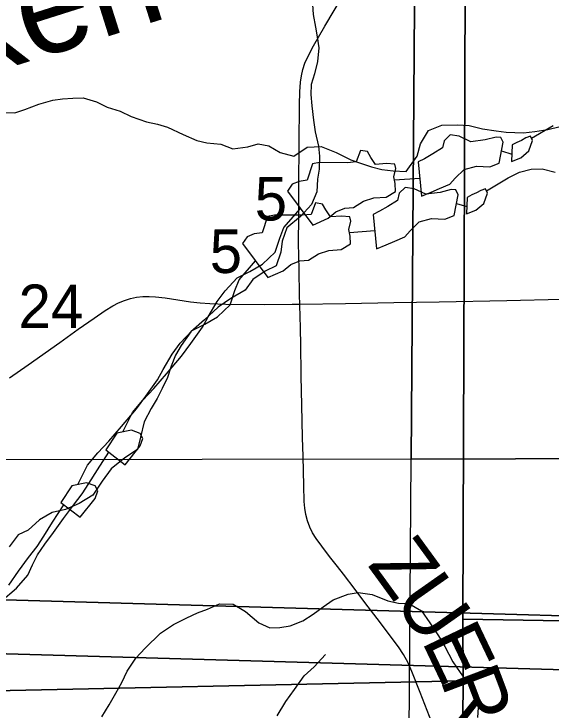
# Model space of a CAD drawing. Extents: x -21.1 to 50.3, y -4.9 to 22.1.
# Drawn here: x 4.071 to 4.587, y 17.902 to 18.571 of the extents above; entities that cross this region are included whole.
import ezdxf

# ---------------------------------------------------------------- set-up
doc = ezdxf.new("R2010")
doc.units = 0
for name, color, linetype in [('GM_X_County_Road', 7, 'Continuous'), ('GM_X_Minor_Lake', 7, 'Continuous'), ('GM_X_Minor_River', 7, 'Continuous'), ('GM_X_Minor_River_Text', 7, 'Continuous'), ('GM_X_Section', 7, 'Continuous'), ('GM_X_Section_Text', 7, 'Continuous'), ('GM_X_Township_Road', 7, 'Continuous'), ('GM_X_Township_Road_Text', 7, 'Continuous')]:
    doc.layers.add(name, color=color, linetype=linetype)

msp = doc.modelspace()

# ---------------------------------------------------------------- linework, layer by layer
at = {"layer": 'GM_X_County_Road'}
for points in [[(4.06655, 18.22107), (4.08439, 18.23347), (4.11483, 18.25489), (4.13257, 18.26786), (4.1479, 18.27834), (4.15838, 18.28565), (4.16583, 18.29006), (4.17135, 18.29295), (4.17698, 18.29535), (4.18275, 18.29722), (4.18872, 18.29843), (4.19477, 18.29909), (4.20088, 18.29926), (4.20699, 18.29899), (4.21614, 18.29795), (4.2406, 18.29407), (4.24986, 18.29298), (4.25917, 18.2923), (4.27471, 18.29175), (4.31197, 18.29148), (4.33843, 18.29178), (4.3458, 18.29178)], [(4.3458, 18.29178), (4.3896, 18.29249), (4.43621, 18.29326), (4.4797, 18.29415), (4.54492, 18.29528), (4.59772, 18.29648)]]:
    msp.add_lwpolyline(points, dxfattribs=at)
at = {"layer": 'GM_X_Minor_Lake'}
for points in [[(4.46292, 18.3955), (4.47198, 18.39939), (4.48028, 18.4029), (4.49009, 18.40718), (4.49534, 18.41293), (4.50397, 18.42137), (4.51569, 18.42453), (4.52859, 18.42391), (4.53765, 18.42742), (4.54122, 18.44757), (4.53927, 18.4521), (4.53472, 18.45243), (4.52413, 18.44966), (4.51012, 18.44799), (4.49906, 18.45319), (4.49032, 18.45461), (4.4847, 18.44886), (4.48288, 18.44201), (4.47384, 18.43622), (4.46555, 18.43158), (4.45952, 18.42848)], [(4.54939, 18.42906), (4.55845, 18.43257), (4.56596, 18.43911), (4.56965, 18.44901), (4.5677, 18.45316), (4.56317, 18.4516), (4.55902, 18.44927), (4.55449, 18.44733), (4.54997, 18.445)], [(4.35818, 18.36782), (4.3729, 18.37443), (4.38041, 18.38058), (4.3891, 18.38409), (4.39743, 18.38456), (4.40685, 18.39073), (4.41705, 18.39387), (4.4288, 18.39476), (4.43784, 18.40017), (4.43737, 18.40775), (4.43616, 18.41419), (4.43797, 18.42217), (4.43716, 18.42634), (4.42919, 18.42701), (4.41858, 18.42614), (4.41396, 18.43292), (4.41086, 18.43858), (4.40402, 18.43965), (4.39997, 18.4286), (4.39164, 18.42775), (4.36471, 18.42784), (4.3579, 18.42663), (4.35276, 18.41102), (4.34519, 18.4098), (4.3384, 18.40707), (4.33392, 18.40057)], [(4.54997, 18.445), (4.54939, 18.42906)], [(4.45952, 18.42848), (4.46292, 18.3955)], [(4.33392, 18.40057), (4.35818, 18.36782)], [(4.41963, 18.34499), (4.42869, 18.34888), (4.43699, 18.35238), (4.44681, 18.35666), (4.45205, 18.36241), (4.46068, 18.37085), (4.4724, 18.37401), (4.4853, 18.37339), (4.49436, 18.3769), (4.49793, 18.39705), (4.49598, 18.40158), (4.49143, 18.40191), (4.48084, 18.39915), (4.46683, 18.39748), (4.45577, 18.40267), (4.44703, 18.40409), (4.44141, 18.39834), (4.43959, 18.39149), (4.43055, 18.3857), (4.42226, 18.38106), (4.41623, 18.37796)], [(4.5061, 18.37855), (4.51516, 18.38206), (4.52267, 18.38859), (4.52636, 18.3985), (4.52441, 18.40265), (4.51988, 18.40108), (4.51573, 18.39876), (4.5112, 18.39681), (4.50668, 18.39449)], [(4.50668, 18.39449), (4.5061, 18.37855)], [(4.31489, 18.3173), (4.32961, 18.32391), (4.33712, 18.33006), (4.34581, 18.33357), (4.35414, 18.33404), (4.36356, 18.34021), (4.37376, 18.34336), (4.38551, 18.34424), (4.39455, 18.34965), (4.39408, 18.35723), (4.39288, 18.36367), (4.39468, 18.37166), (4.39388, 18.37582), (4.3859, 18.3765), (4.37529, 18.37563), (4.37067, 18.3824), (4.36757, 18.38807), (4.36073, 18.38913), (4.35668, 18.37808), (4.34835, 18.37723), (4.32142, 18.37732), (4.31461, 18.37611), (4.30948, 18.3605), (4.30191, 18.35928), (4.29511, 18.35655), (4.29063, 18.35005)], [(4.41623, 18.37796), (4.41963, 18.34499)], [(4.29063, 18.35005), (4.31489, 18.3173)], [(4.17759, 18.13746), (4.19218, 18.15545), (4.19475, 18.16268), (4.19204, 18.16759), (4.18367, 18.17053), (4.16967, 18.16773), (4.15923, 18.15168)], [(4.15923, 18.15168), (4.17759, 18.13746)], [(4.1343, 18.08694), (4.14889, 18.10493), (4.15146, 18.11217), (4.14875, 18.11707), (4.14038, 18.12002), (4.12638, 18.11721), (4.11594, 18.10116)], [(4.11594, 18.10116), (4.1343, 18.08694)]]:
    msp.add_lwpolyline(points, dxfattribs=at)
at = {"layer": 'GM_X_Minor_River'}
for points in [[(4.35796, 18.57986), (4.35871, 18.57038), (4.36098, 18.55824), (4.36249, 18.54876), (4.364, 18.53814), (4.36286, 18.52524), (4.35982, 18.51311), (4.35678, 18.50287), (4.3564, 18.49338), (4.35715, 18.48239), (4.35904, 18.46873), (4.36055, 18.45736), (4.36358, 18.4437), (4.36471, 18.43422), (4.36432, 18.4217), (4.3628, 18.41184), (4.36204, 18.39971), (4.3571, 18.38757), (4.34648, 18.37619), (4.33321, 18.36519), (4.32865, 18.35229), (4.32751, 18.34167), (4.32295, 18.32878), (4.31234, 18.32347), (4.30058, 18.3155), (4.293, 18.30526), (4.27935, 18.29729), (4.26721, 18.28895), (4.25394, 18.27681), (4.24104, 18.26505), (4.23156, 18.25215), (4.22625, 18.24267), (4.22207, 18.23205), (4.21828, 18.22143), (4.21334, 18.21081), (4.20841, 18.20095), (4.20272, 18.19147), (4.19589, 18.17857), (4.19247, 18.16378), (4.18943, 18.15202), (4.1773, 18.14406), (4.1644, 18.13344), (4.15568, 18.12168), (4.14658, 18.10802), (4.1333, 18.10005), (4.12041, 18.09437), (4.10752, 18.09133), (4.09539, 18.0845), (4.08439, 18.07464), (4.07491, 18.07009), (4.06619, 18.05833)], [(4.05737, 18.47617), (4.07141, 18.47565), (4.08131, 18.47896), (4.09465, 18.48415), (4.10798, 18.48781), (4.11748, 18.48923), (4.12736, 18.48989), (4.13723, 18.49017), (4.15009, 18.48624), (4.16029, 18.4812), (4.17278, 18.47728), (4.18336, 18.47223), (4.19811, 18.46715), (4.20871, 18.46476), (4.21855, 18.462), (4.23367, 18.45501), (4.24651, 18.44918), (4.25636, 18.4468), (4.26963, 18.44553), (4.28135, 18.44123), (4.2958, 18.44298), (4.3057, 18.44592), (4.31592, 18.44392), (4.32687, 18.43773), (4.34012, 18.43418), (4.35274, 18.44279), (4.36641, 18.44341), (4.38077, 18.43757), (4.39474, 18.43059), (4.40496, 18.42706), (4.4148, 18.42393), (4.42464, 18.42117), (4.43563, 18.41992), (4.44815, 18.41941), (4.45856, 18.43412), (4.46171, 18.44586), (4.46944, 18.4587), (4.4824, 18.46389), (4.49758, 18.46411), (4.50859, 18.46362), (4.52146, 18.46045), (4.53473, 18.45842), (4.5442, 18.45718), (4.5609, 18.45663), (4.57192, 18.45766), (4.58447, 18.45981), (4.59627, 18.46273)], [(4.56859, 18.45127), (4.58958, 18.46364)], [(4.53971, 18.43907), (4.54965, 18.4361)], [(4.5253, 18.40075), (4.54629, 18.41313), (4.55723, 18.41856), (4.56819, 18.42171), (4.57881, 18.42182), (4.59136, 18.41854)], [(4.43673, 18.41119), (4.46111, 18.41304)], [(4.49642, 18.38855), (4.50636, 18.38559)], [(4.17553, 18.1689), (4.18461, 18.18762), (4.19472, 18.19949), (4.20521, 18.21061), (4.21757, 18.22478), (4.23179, 18.24163), (4.24076, 18.25386), (4.25196, 18.26954), (4.25754, 18.27947), (4.26609, 18.29436), (4.27394, 18.30469), (4.28556, 18.31695), (4.29762, 18.32315), (4.30968, 18.33011), (4.32207, 18.34163), (4.32647, 18.35534), (4.33052, 18.36563), (4.34626, 18.38391)], [(4.39344, 18.36067), (4.41782, 18.36252)], [(4.13224, 18.11839), (4.14132, 18.1371), (4.15143, 18.14897), (4.16192, 18.16009), (4.17428, 18.17426), (4.1885, 18.19111), (4.19747, 18.20335), (4.20867, 18.21903), (4.21425, 18.22895), (4.2228, 18.24384), (4.23065, 18.25417), (4.24227, 18.26644), (4.25433, 18.27264), (4.26639, 18.2796), (4.27878, 18.29111), (4.28318, 18.30482), (4.28723, 18.31511), (4.30298, 18.33339)], [(4.05809, 18.00602), (4.07311, 18.01871), (4.08397, 18.03134), (4.08841, 18.04126), (4.09323, 18.0508), (4.10033, 18.06112), (4.10892, 18.07221), (4.11825, 18.08559), (4.12797, 18.0986), (4.13619, 18.10931), (4.14291, 18.11925), (4.1511, 18.13262), (4.16212, 18.14944)], [(4.06563, 18.0217), (4.07496, 18.03508), (4.08468, 18.04808), (4.0929, 18.0588), (4.09962, 18.06873), (4.10781, 18.0821), (4.11883, 18.09892)], [(4.15534, 17.89495), (4.16235, 17.90662), (4.16861, 17.91792), (4.17446, 17.92809), (4.17957, 17.93902), (4.18812, 17.95143), (4.197, 17.96118), (4.21166, 17.97539), (4.22432, 17.98393), (4.23695, 17.9902), (4.24728, 17.99498), (4.25684, 17.99864), (4.26831, 18.00378), (4.28159, 18.0032), (4.29364, 17.99618), (4.30639, 17.98535), (4.31695, 17.98063), (4.32645, 17.98086), (4.33635, 17.98261), (4.34858, 17.98737), (4.35855, 17.99367), (4.36816, 18.00075), (4.37775, 18.00744), (4.39227, 18.01292), (4.40179, 18.01467), (4.41544, 18.01257), (4.43054, 18.00664), (4.44075, 18.0042), (4.45063, 18.00405), (4.46267, 17.99704), (4.47085, 17.98551), (4.47901, 17.97285), (4.48531, 17.9625), (4.49306, 17.94795), (4.50011, 17.93758), (4.50755, 17.92683), (4.51422, 17.91647), (4.51745, 17.90389), (4.51654, 17.89441)], [(4.32387, 17.89603), (4.33221, 17.90969), (4.34056, 17.92144), (4.35004, 17.93434), (4.35952, 17.94307), (4.37052, 17.95482)]]:
    msp.add_lwpolyline(points, dxfattribs=at)
at = {"layer": 'GM_X_Section'}
for points in [[(3.45029, 19.15441), (4.46024, 19.14326), (4.45293, 18.14262), (3.44648, 18.14125)], [(4.46024, 19.14326), (5.46172, 19.1492), (5.45742, 18.14589), (4.45293, 18.14262)], [(3.83539, 19.00471), (4.83075, 19.0046), (4.83425, 17.98542), (3.80452, 18.01477), (3.80166, 19.0044)], [(5.47114, 18.99721), (5.48815, 17.97251), (4.50247, 17.98887), (4.50596, 18.94006), (4.50668, 19.00183)], [(3.7921, 18.95419), (4.78746, 18.95409), (4.79096, 17.9349), (3.76124, 17.96425), (3.75837, 18.95389)], [(4.50596, 18.94006), (4.50247, 17.98887), (4.50289, 17.92975), (3.48086, 17.90781), (3.48506, 18.92038)], [(4.45293, 18.14262), (5.45742, 18.14589), (5.45266, 17.13084), (4.44556, 17.13365)], [(3.80452, 18.01477), (4.83425, 17.98542), (4.84683, 16.96859), (4.43354, 16.98495), (3.82173, 16.99041)], [(4.50247, 17.98887), (5.48815, 17.97251), (5.52017, 16.94387), (4.49435, 16.93023), (4.50289, 17.92975)], [(3.76124, 17.96425), (4.79096, 17.9349), (4.80354, 16.91807), (4.39025, 16.93443), (3.77844, 16.93989)], [(3.48086, 17.90781), (4.50289, 17.92975), (4.49435, 16.93023), (4.49436, 16.90218), (3.4856, 16.89423)]]:
    msp.add_lwpolyline(points, close=True, dxfattribs=at)
at = {"layer": 'GM_X_Township_Road'}
for points in [[(4.3458, 18.29178), (4.34537, 18.30008), (4.34508, 18.32499), (4.34463, 18.35065), (4.34479, 18.3754), (4.34495, 18.40589), (4.34519, 18.44623), (4.34533, 18.48354), (4.34566, 18.49597), (4.34642, 18.50526), (4.34732, 18.51142), (4.34868, 18.51748), (4.35068, 18.52335), (4.3532, 18.52903), (4.35892, 18.54008), (4.36977, 18.55894), (4.38881, 18.59102)], [(4.34662, 18.25449), (4.34642, 18.26642), (4.34613, 18.28257), (4.34582, 18.28816), (4.3458, 18.29178)], [(4.47282, 17.88961), (4.4614, 17.91849), (4.45335, 17.93869), (4.44986, 17.94701), (4.44564, 17.95486), (4.44082, 17.96241), (4.43082, 17.97537), (4.42339, 17.98525), (4.40832, 18.00496), (4.39894, 18.01735), (4.38773, 18.03211), (4.38205, 18.03942), (4.37442, 18.04913), (4.3669, 18.05898), (4.3614, 18.06653), (4.35806, 18.07185), (4.35527, 18.0775), (4.35307, 18.0834), (4.35146, 18.08948), (4.35043, 18.09568), (4.34994, 18.10192), (4.34946, 18.11741), (4.34896, 18.14519), (4.34838, 18.16375), (4.34763, 18.1948), (4.34716, 18.22265), (4.34662, 18.25449)]]:
    msp.add_lwpolyline(points, dxfattribs=at)

# ---------------------------------------------------------------- texts
at = {"layer": 'GM_X_Minor_River_Text'}
msp.add_text('Broken', height=0.094723, rotation=17.56941, dxfattribs=at).set_placement((3.8381, 18.44685))
at = {"layer": 'GM_X_Section_Text'}
for s, height, p in [('5', 0.04186, (4.30235, 18.37224)), ('5', 0.04186, (4.25906, 18.32172)), ('24', 0.041856, (4.07512, 18.2688))]:
    msp.add_text(s, height=height, rotation=0.00001, dxfattribs=at).set_placement(p)
at = {"layer": 'GM_X_Township_Road_Text'}
for s, rotation, p in [('Z', 306.0989, (4.41023, 18.04113)), ('U', 305.02784, (4.43511, 18.00702)), ('E', 295.46391, (4.46255, 17.96824)), ('R', 290.7084, (4.48033, 17.93102))]:
    msp.add_text(s, height=0.05682, rotation=rotation, dxfattribs=at).set_placement(p)

doc.saveas('drawing.dxf')
